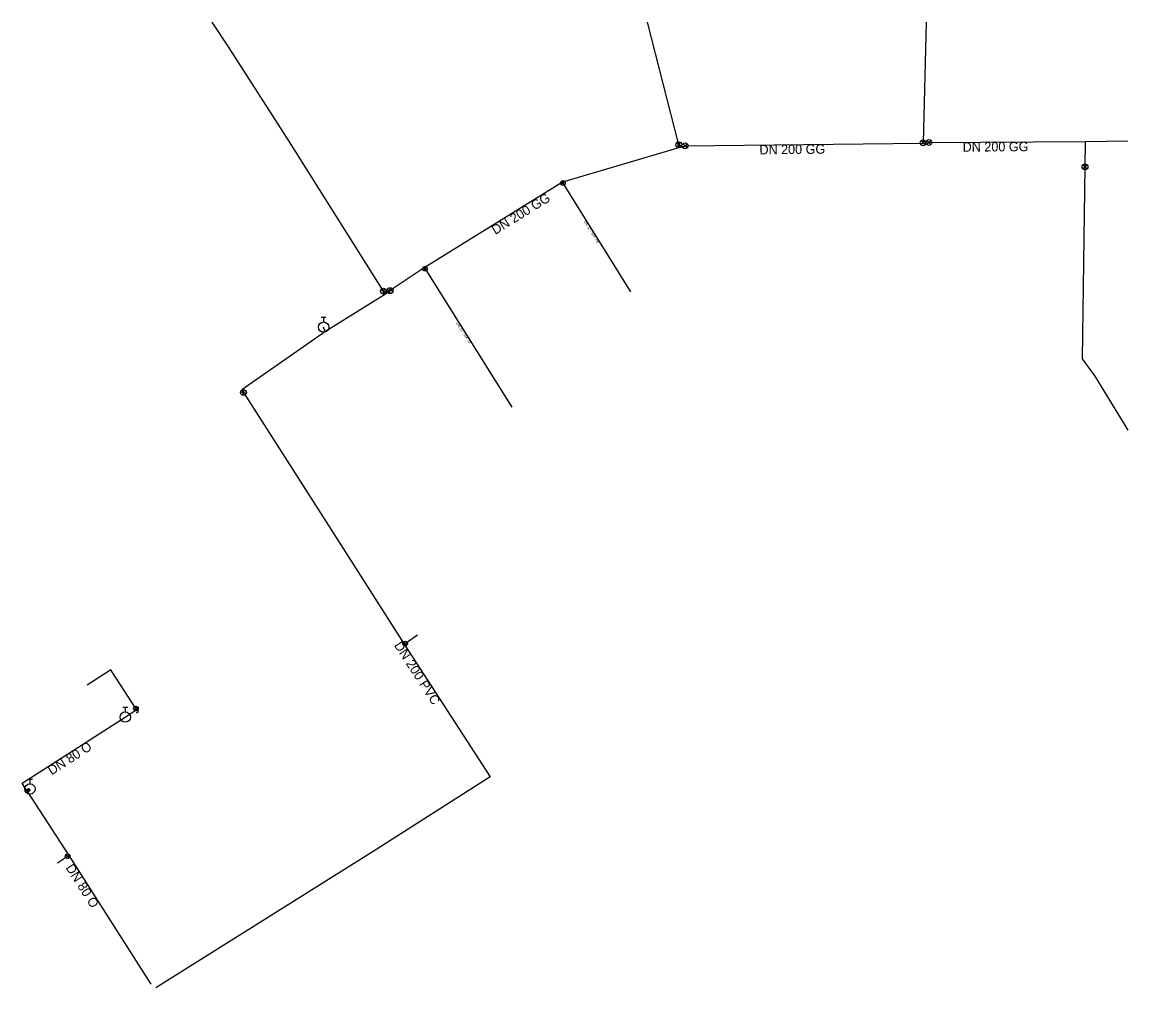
# Model space of a CAD drawing. Extents: x -451199 to -450721, y -1101768 to -1101453.
# Drawn here: x -450909.4 to -450720.9, y -1101617.4 to -1101452.7 of the extents above; entities that cross this region are included whole.
import ezdxf

# ---------------------------------------------------------------- set-up
doc = ezdxf.new("R2010")
doc.units = 0
for name, color, linetype in [('_hydrantova_odbocka_', 7, 'Continuous'), ('_pripojka_prevzato_z_dokumentace_', 7, 'Continuous'), ('_pripojka_priblizne_', 7, 'Continuous'), ('_voda_smvak_prevzato_z_dokumentace_', 7, 'Continuous'), ('Default', 7, 'Continuous'), ('MoLevel 27', 7, 'Continuous'), ('MoLevel 28', 7, 'Continuous'), ('MoLevel 43', 7, 'Continuous'), ('MoLevel 46', 7, 'Continuous'), ('MoLevel 53', 7, 'Continuous'), ('MoLevel 55', 7, 'Continuous')]:
    doc.layers.add(name, color=color, linetype=linetype)

# ---------------------------------------------------------------- blocks, each defined once
blk = doc.blocks.new('_uzaver_')
at = {"layer": 'Default'}
for p, q in [((-0.000035, -0.000035), (0.000035, 0.000035)), ((0.000035, -0.000035), (-0.000035, 0.000035))]:
    blk.add_line(p, q, dxfattribs=at)
for radius in [0.00005, 0.0000025]:
    blk.add_circle((0, 0), radius, dxfattribs=at)
blk = doc.blocks.new('_uzaver_pripojka_')
at = {"layer": 'Default'}
for p, q in [((-0.000035, -0.000035), (0.000035, 0.000035)), ((0.000035, -0.000035), (-0.000035, 0.000035))]:
    blk.add_line(p, q, dxfattribs=at)
for radius in [0.00005, 0.0000025]:
    blk.add_circle((0, 0), radius, dxfattribs=at)
blk = doc.blocks.new('_hydrant_voda_')
at = {"layer": 'Default'}
for p, q in [((-0.000023, 0.000095), (0.000023, 0.000095)), ((0, 0.000095), (0, 0.00005))]:
    blk.add_line(p, q, dxfattribs=at)
blk.add_circle((0, 0), 0.00005, dxfattribs=at)
blk = doc.blocks.new('_zaslepeni_')
at = {"layer": 'Default'}
blk.add_lwpolyline([(-0.00004, -0.00005), (0, -0.00005), (0, 0.00005), (-0.00004, 0.00005), (-0.00004, 0.00005)], dxfattribs=at)

msp = doc.modelspace()

# ---------------------------------------------------------------- linework, layer by layer
at = {"layer": '_hydrantova_odbocka_'}
for points in [[(-450857.68, -1101505.41), (-450857.92, -1101505.04), (-450858.01, -1101504.69)], [(-450908.07, -1101583.46), (-450908.34, -1101583.64), (-450908.59, -1101583.77)]]:
    msp.add_lwpolyline(points, dxfattribs=at)
at = {"layer": '_pripojka_prevzato_z_dokumentace_'}
for points in [[(-450817.27, -1101479.99), (-450817.21, -1101480.12), (-450805.67, -1101498.65)], [(-450840.83, -1101494.6), (-450840.71, -1101494.73), (-450825.92, -1101518.35)], [(-450844.27, -1101558.75), (-450844.1, -1101558.65), (-450842.02, -1101557.18)], [(-450903.37, -1101596.06), (-450901.66, -1101594.93), (-450901.46, -1101594.82)]]:
    msp.add_lwpolyline(points, dxfattribs=at)
at = {"layer": '_pripojka_priblizne_'}
for points in [[(-450893.99, -1101563.58), (-450894.26, -1101563.16), (-450898.3, -1101565.73)], [(-450889.88, -1101569.93), (-450890.02, -1101569.75), (-450893.99, -1101563.58)]]:
    msp.add_lwpolyline(points, dxfattribs=at)
at = {"layer": '_voda_smvak_prevzato_z_dokumentace_'}
for p, q in [((-450797.45, -1101473.58), (-450802.8, -1101452.67)), ((-450755.27, -1101452.67), (-450755.79, -1101473.25)), ((-450797.24, -1101474.05), (-450797.45, -1101473.58)), ((-450796.36, -1101473.76), (-450755.86, -1101473.34)), ((-450755.86, -1101473.34), (-450754.8, -1101473.21)), ((-450755.79, -1101473.25), (-450755.86, -1101473.34)), ((-450754.8, -1101473.21), (-450728.15, -1101473.01)), ((-450728.15, -1101473.01), (-450728.18, -1101477.35)), ((-450728.15, -1101473.01), (-450720.86, -1101472.9)), ((-450797.24, -1101474.05), (-450796.36, -1101473.76)), ((-450847.43, -1101499.07), (-450847.79, -1101498.56)), ((-450846.67, -1101498.47), (-450847.43, -1101499.07)), ((-450871.66, -1101515.85), (-450857.18, -1101538.52))]:
    msp.add_line(p, q, dxfattribs=at)
for points in [[(-450847.79, -1101498.56), (-450863.83, -1101473.07), (-450874.13, -1101457.03), (-450877.01, -1101452.67)], [(-450797.24, -1101474.05), (-450817.27, -1101479.99), (-450840.83, -1101494.6), (-450846.67, -1101498.47)], [(-450728.18, -1101477.35), (-450728.68, -1101510.09), (-450726.5, -1101513.08), (-450720.86, -1101522.29)], [(-450847.43, -1101499.07), (-450857.68, -1101505.41), (-450871.94, -1101515.4), (-450871.66, -1101515.85)], [(-450857.18, -1101538.52), (-450844.27, -1101558.75), (-450829.62, -1101581.39), (-450849.55, -1101594.12), (-450886.63, -1101617.38)], [(-450908.59, -1101583.77), (-450909.41, -1101582.47), (-450891.82, -1101571.19), (-450889.77, -1101569.86)], [(-450908.59, -1101583.77), (-450901.46, -1101594.82), (-450887.47, -1101616.76)]]:
    msp.add_lwpolyline(points, dxfattribs=at)

# ---------------------------------------------------------------- block references
at = {"layer": 'MoLevel 27'}
for p, xscale, yscale, rotation in [((-450797.45, -1101473.58), 10000, 10000, 104.326737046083), ((-450796.36, -1101473.76), 10000, 9999.999999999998, 0.594157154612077), ((-450755.79, -1101473.25), 9999.999999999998, 10000.000000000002, 88.5507842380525), ((-450754.8, -1101473.21), 10000, 10000, 0.41734959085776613), ((-450728.18, -1101477.35), 10000, 10000.000000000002, 89.5950599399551), ((-450847.79, -1101498.56), 9999.999999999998, 10000.000000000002, 122.17577550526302), ((-450846.67, -1101498.47), 10000, 10000, 33.53129107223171), ((-450871.66, -1101515.85), 10000, 9999.999999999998, -57.439240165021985)]:
    msp.add_blockref('_uzaver_', p, dxfattribs=dict(at, xscale=xscale, yscale=yscale, rotation=rotation))
at = {"layer": 'MoLevel 27', "xscale": 5000, "yscale": 5000}
msp.add_blockref('_uzaver_', (-450908.34, -1101583.64), dxfattribs=at)
at = {"layer": 'MoLevel 28', "xscale": 17636.68430335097, "yscale": 17636.68430335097}
for p in [(-450858.01, -1101504.69), (-450891.82, -1101571.19), (-450908.07, -1101583.46)]:
    msp.add_blockref('_hydrant_voda_', p, dxfattribs=at)
at = {"layer": 'MoLevel 43', "xscale": 10000, "yscale": 9999.999999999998, "rotation": 25.5524611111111}
msp.add_blockref('_zaslepeni_', (-450889.77, -1101569.86), dxfattribs=at)
at = {"layer": 'MoLevel 53', "xscale": 7999.999999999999, "yscale": 7999.999999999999}
for p in [(-450817.21, -1101480.12), (-450840.71, -1101494.73), (-450844.1, -1101558.65), (-450890.02, -1101569.75), (-450901.66, -1101594.93)]:
    msp.add_blockref('_uzaver_pripojka_', p, dxfattribs=at)

# ---------------------------------------------------------------- texts
at = {"layer": 'MoLevel 46'}
for s, rotation, p in [('DN 200 GG', 0.5942, (-450783.68, -1101475.23)), ('DN 200 GG', 0.43, (-450749.03, -1101474.77)), ('DN 200 GG', 31.8038, (-450828.72, -1101488.98)), ('DN 200 PVC', 302.9063, (-450846.05, -1101558.95)), ('DN 80 O', 32.6519, (-450904.38, -1101581.15)), ('DN 80 O', 302.5236, (-450902.05, -1101596.88))]:
    msp.add_text(s, height=1.605, rotation=rotation, dxfattribs=at).set_placement(p)
at = {"layer": 'MoLevel 55'}
for s, rotation, p in [("DN 32 - 5/4'' PE", 301.9136, (-450813.66, -1101486.69)), ("DN 32 - 5/4'' O", 302.0533, (-450835.44, -1101504.01))]:
    msp.add_text(s, height=0.455, rotation=rotation, dxfattribs=at).set_placement(p)

doc.saveas('drawing.dxf')
